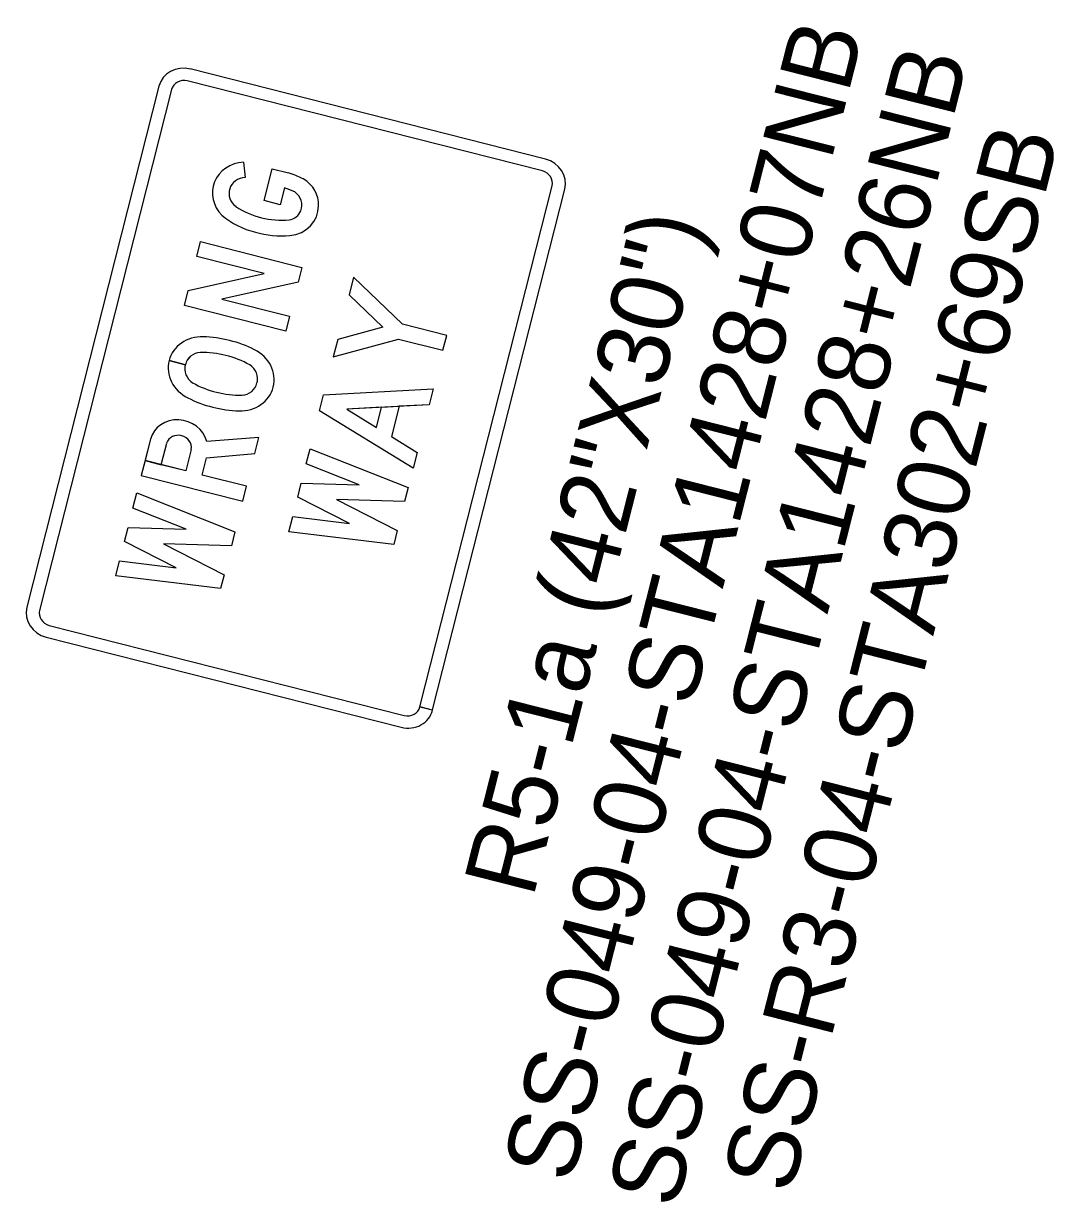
# Model space of a CAD drawing. Extents: x 670257 to 671518, y 737783 to 738188.
# Drawn here: x 670275.413 to 670279.004, y 738123.258 to 738127.359 of the extents above; entities that cross this region are included whole.
import ezdxf

# ---------------------------------------------------------------- set-up
doc = ezdxf.new("R2010")
doc.units = 0
for name, color, linetype in [('GSBWFILL', 7, 'Continuous'), ('GSCOLORFILL', 7, 'Continuous'), ('GSOUTLINE', 7, 'Continuous'), ('R_SIGN_ANNOT', 7, 'Continuous')]:
    doc.layers.add(name, color=color, linetype=linetype)

msp = doc.modelspace()

# ---------------------------------------------------------------- linework, layer by layer
at = {"layer": 'GSBWFILL'}
for p, q in [((670276.1786, 738126.8766), (670276.1849, 738126.8225)), ((670276.1849, 738126.8225), (670276.1849, 738126.8225)), ((670275.9765, 738126.1716), (670275.9196, 738126.186)), ((670275.9196, 738126.186), (670275.9765, 738126.1716)), ((670275.9765, 738126.1716), (670275.9765, 738126.1716))]:
    msp.add_line(p, q, dxfattribs=at)
for points in [[(670276.3216, 738126.7868), (670276.3067, 738126.7282), (670276.2503, 738126.7425), (670276.2784, 738126.8536), (670276.3349, 738126.8393)], [(670275.855, 738125.913), (670275.8361, 738125.8382), (670275.8925, 738125.8239), (670275.9115, 738125.8987)], [(670276.1759, 738125.6967), (670276.189, 738125.7487), (670276.0347, 738125.7878), (670276.05, 738125.8482), (670276.2181, 738125.8634), (670276.2322, 738125.919), (670276.051, 738125.9048)], [(670275.9972, 738125.877), (670275.9782, 738125.8021), (670275.8361, 738125.8382), (670275.8229, 738125.7862), (670276.1759, 738125.6967)]]:
    msp.add_lwpolyline(points, dxfattribs=at)
for points in [[(670276.3259, 738126.2882), (670275.9729, 738126.3777), (670275.9862, 738126.4302), (670276.2511, 738126.4885), (670276.0161, 738126.5481), (670276.0293, 738126.6), (670276.3822, 738126.5105), (670276.3691, 738126.4585), (670276.1028, 738126.4), (670276.339, 738126.3401)], [(670276.4911, 738126.1988), (670276.7183, 738126.2612), (670276.8727, 738126.2221), (670276.8858, 738126.2739), (670276.7315, 738126.313), (670276.5615, 738126.4762), (670276.546, 738126.4152), (670276.6632, 738126.3028), (670276.5066, 738126.2597)], [(670276.7686, 738125.8118), (670276.4436, 738126.0117), (670276.4576, 738126.0668), (670276.8386, 738126.0876), (670276.8247, 738126.0327), (670276.5378, 738126.0171), (670276.6412, 738125.9535), (670276.659, 738126.0237), (670276.72, 738126.027), (670276.6932, 738125.9215), (670276.7825, 738125.8666)], [(670276.5475, 738125.6194), (670276.3674, 738125.7109), (670276.3797, 738125.7596), (670276.5816, 738125.7542), (670276.3969, 738125.8272), (670276.4102, 738125.8796), (670276.7516, 738125.7447), (670276.7393, 738125.6961), (670276.5027, 738125.7025), (670276.7137, 738125.5953), (670276.7014, 738125.5467), (670276.3369, 738125.5908), (670276.3502, 738125.6433)], [(670275.9448, 738125.4654), (670275.7647, 738125.5569), (670275.7771, 738125.6056), (670275.979, 738125.6002), (670275.7942, 738125.6732), (670275.8075, 738125.7257), (670276.149, 738125.5907), (670276.1367, 738125.5421), (670275.9001, 738125.5485), (670276.1111, 738125.4413), (670276.0988, 738125.3927), (670275.7343, 738125.4368), (670275.7476, 738125.4893)]]:
    msp.add_lwpolyline(points, close=True, dxfattribs=at)
for centre, major_axis, start_param, end_param in [((670276.1912, 738126.7651), (-0.1173, 0.0297), 5.047079, 7.269538), ((670276.1896, 738126.7657), (-0.0597, 0.0151), 5.019133, 7.435888), ((670276.2475, 738126.5727), (-0.2958, 0.075), 4.464985, 4.64968), ((670276.3345, 738126.7355), (-0.1022, 0.0259), 3.298379, 4.420063), ((670276.2721, 738126.6219), (-0.1816, 0.0461), 4.467103, 4.672764), ((670276.3219, 738126.7293), (-0.0582, 0.0148), 3.004204, 4.309319), ((670276.3002, 738126.9211), (-0.2585, 0.0656), 1.210526, 1.939684), ((670276.3266, 738126.7261), (-0.1098, 0.0278), 1.917608, 3.396087), ((670276.2784, 738126.8716), (-0.2593, 0.0658), 1.08427, 1.578846), ((670276.3286, 738126.723), (-0.05, 0.0127), 1.967991, 3.075152), ((670276.2971, 738126.8991), (-0.2924, 0.0742), 1.54039, 1.942608), ((670276.0388, 738126.155), (-0.1194, 0.0303), 4.940915, 6.27603), ((670276.0442, 738125.9235), (-0.3622, 0.0919), 4.707364, 4.955713), ((670276.0478, 738125.9226), (-0.3622, 0.0919), 4.469065, 4.717414), ((670276.0358, 738126.1584), (-0.059, 0.015), 5.062003, 6.313732), ((670276.0489, 738125.9612), (-0.2657, 0.0674), 4.688261, 5.016143), ((670276.0617, 738125.9579), (-0.2657, 0.0674), 4.408635, 4.736517), ((670276.1629, 738126.1236), (-0.1194, 0.0303), 3.1486, 4.483863), ((670276.0392, 738126.1566), (-0.1194, 0.0303), 0.007008, 1.34227), ((670276.0349, 738126.1551), (-0.059, 0.015), 6.252339, 7.504367), ((670276.1672, 738126.1251), (-0.059, 0.015), 3.110746, 4.362775), ((670276.1404, 738126.3222), (-0.2657, 0.0674), 1.267042, 1.594924), ((670276.1663, 738126.1217), (-0.059, 0.015), 1.920411, 3.172439), ((670276.1533, 738126.319), (-0.2657, 0.0674), 1.546668, 1.87455), ((670276.1633, 738126.1251), (-0.1194, 0.0303), 1.799323, 3.134585), ((670276.1543, 738126.3575), (-0.3622, 0.0919), 1.327472, 1.575821), ((670276.1579, 738126.3566), (-0.3622, 0.0919), 1.565772, 1.814121), ((670275.9529, 738125.8865), (-0.0983, 0.0249), 3.608399, 6.264838), ((670275.9536, 738125.8852), (-0.043, 0.0109), 3.211299, 6.213479)]:
    msp.add_ellipse(centre, major_axis=major_axis, ratio=0.919391, start_param=start_param, end_param=end_param, dxfattribs=at)
at = {"layer": 'GSCOLORFILL'}
for p, q in [((670277.2291, 738126.8871), (670275.9937, 738127.2005)), ((670275.8846, 738127.1405), (670275.425, 738125.3284)), ((670275.8846, 738127.1405), (670275.425, 738125.3284)), ((670277.2187, 738126.846), (670275.9833, 738127.1593)), ((670275.9287, 738127.1293), (670275.4691, 738125.3172)), ((670276.1786, 738126.8766), (670276.1849, 738126.8225)), ((670276.1849, 738126.8225), (670276.1849, 738126.8225)), ((670276.7929, 738124.982), (670277.2524, 738126.7936)), ((670276.837, 738124.9708), (670277.2965, 738126.7824)), ((670275.9765, 738126.1716), (670275.9196, 738126.186)), ((670275.9196, 738126.186), (670275.9765, 738126.1716)), ((670275.9765, 738126.1716), (670275.9765, 738126.1716)), ((670275.5028, 738125.2649), (670276.7382, 738124.9515)), ((670275.4924, 738125.2237), (670276.7278, 738124.9104)), ((670276.8369, 738124.9703), (670276.7928, 738124.9815)), ((670276.7929, 738124.982), (670276.837, 738124.9708))]:
    msp.add_line(p, q, dxfattribs=at)
for points in [[(670276.3216, 738126.7868), (670276.3067, 738126.7282), (670276.2503, 738126.7425), (670276.2784, 738126.8536), (670276.3349, 738126.8393)], [(670275.855, 738125.913), (670275.8361, 738125.8382), (670275.8925, 738125.8239), (670275.9115, 738125.8987)], [(670276.1759, 738125.6967), (670276.189, 738125.7487), (670276.0347, 738125.7878), (670276.05, 738125.8482), (670276.2181, 738125.8634), (670276.2322, 738125.919), (670276.051, 738125.9048)], [(670275.9972, 738125.877), (670275.9782, 738125.8021), (670275.8361, 738125.8382), (670275.8229, 738125.7862), (670276.1759, 738125.6967)]]:
    msp.add_lwpolyline(points, dxfattribs=at)
for points in [[(670276.3259, 738126.2882), (670275.9729, 738126.3777), (670275.9862, 738126.4302), (670276.2511, 738126.4885), (670276.0161, 738126.5481), (670276.0293, 738126.6), (670276.3822, 738126.5105), (670276.3691, 738126.4585), (670276.1028, 738126.4), (670276.339, 738126.3401)], [(670276.4911, 738126.1988), (670276.7183, 738126.2612), (670276.8727, 738126.2221), (670276.8858, 738126.2739), (670276.7315, 738126.313), (670276.5615, 738126.4762), (670276.546, 738126.4152), (670276.6632, 738126.3028), (670276.5066, 738126.2597)], [(670276.7686, 738125.8118), (670276.4436, 738126.0117), (670276.4576, 738126.0668), (670276.8386, 738126.0876), (670276.8247, 738126.0327), (670276.5378, 738126.0171), (670276.6412, 738125.9535), (670276.659, 738126.0237), (670276.72, 738126.027), (670276.6932, 738125.9215), (670276.7825, 738125.8666)], [(670276.5475, 738125.6194), (670276.3674, 738125.7109), (670276.3797, 738125.7596), (670276.5816, 738125.7542), (670276.3969, 738125.8272), (670276.4102, 738125.8796), (670276.7516, 738125.7447), (670276.7393, 738125.6961), (670276.5027, 738125.7025), (670276.7137, 738125.5953), (670276.7014, 738125.5467), (670276.3369, 738125.5908), (670276.3502, 738125.6433)], [(670275.9448, 738125.4654), (670275.7647, 738125.5569), (670275.7771, 738125.6056), (670275.979, 738125.6002), (670275.7942, 738125.6732), (670275.8075, 738125.7257), (670276.149, 738125.5907), (670276.1367, 738125.5421), (670275.9001, 738125.5485), (670276.1111, 738125.4413), (670276.0988, 738125.3927), (670275.7343, 738125.4368), (670275.7476, 738125.4893)]]:
    msp.add_lwpolyline(points, close=True, dxfattribs=at)
for centre, major_axis, ratio, start_param, end_param in [((670275.9728, 738127.1181), (-0.0882, 0.0224), 0.933392, 4.712389, 6.283185), ((670275.9728, 738127.1181), (-0.0882, 0.0224), 0.933392, 4.712389, 6.283185), ((670275.9728, 738127.1181), (-0.0441, 0.0112), 0.933392, 4.712389, 6.283185), ((670277.2082, 738126.8048), (-0.0882, 0.0224), 0.933392, 3.141593, 4.712389), ((670276.1912, 738126.7651), (-0.1173, 0.0297), 0.919391, 5.047079, 7.269538), ((670277.2082, 738126.8048), (-0.0441, 0.0112), 0.933392, 3.141593, 4.712389), ((670276.1896, 738126.7657), (-0.0597, 0.0151), 0.919391, 5.019133, 7.435888), ((670276.2475, 738126.5727), (-0.2958, 0.075), 0.919391, 4.464985, 4.64968), ((670276.3345, 738126.7355), (-0.1022, 0.0259), 0.919391, 3.298379, 4.420063), ((670276.2721, 738126.6219), (-0.1816, 0.0461), 0.919391, 4.467103, 4.672764), ((670276.3219, 738126.7293), (-0.0582, 0.0148), 0.919391, 3.004204, 4.309319), ((670276.3002, 738126.9211), (-0.2585, 0.0656), 0.919391, 1.210526, 1.939684), ((670276.3266, 738126.7261), (-0.1098, 0.0278), 0.919391, 1.917608, 3.396087), ((670276.2784, 738126.8716), (-0.2593, 0.0658), 0.919391, 1.08427, 1.578846), ((670276.3286, 738126.723), (-0.05, 0.0127), 0.919391, 1.967991, 3.075152), ((670276.2971, 738126.8991), (-0.2924, 0.0742), 0.919391, 1.54039, 1.942608), ((670276.0388, 738126.155), (-0.1194, 0.0303), 0.919391, 4.940915, 6.27603), ((670276.0442, 738125.9235), (-0.3622, 0.0919), 0.919391, 4.707364, 4.955713), ((670276.0478, 738125.9226), (-0.3622, 0.0919), 0.919391, 4.469065, 4.717414), ((670276.0358, 738126.1584), (-0.059, 0.015), 0.919391, 5.062003, 6.313732), ((670276.0489, 738125.9612), (-0.2657, 0.0674), 0.919391, 4.688261, 5.016143), ((670276.0617, 738125.9579), (-0.2657, 0.0674), 0.919391, 4.408635, 4.736517), ((670276.1629, 738126.1236), (-0.1194, 0.0303), 0.919391, 3.1486, 4.483863), ((670276.0392, 738126.1566), (-0.1194, 0.0303), 0.919391, 0.007008, 1.34227), ((670276.0349, 738126.1551), (-0.059, 0.015), 0.919391, 6.252339, 7.504367), ((670276.1672, 738126.1251), (-0.059, 0.015), 0.919391, 3.110746, 4.362775), ((670276.1404, 738126.3222), (-0.2657, 0.0674), 0.919391, 1.267042, 1.594924), ((670276.1663, 738126.1217), (-0.059, 0.015), 0.919391, 1.920411, 3.172439), ((670276.1533, 738126.319), (-0.2657, 0.0674), 0.919391, 1.546668, 1.87455), ((670276.1633, 738126.1251), (-0.1194, 0.0303), 0.919391, 1.799323, 3.134585), ((670276.1543, 738126.3575), (-0.3622, 0.0919), 0.919391, 1.327472, 1.575821), ((670276.1579, 738126.3566), (-0.3622, 0.0919), 0.919391, 1.565772, 1.814121), ((670275.9529, 738125.8865), (-0.0983, 0.0249), 0.919391, 3.608399, 6.264838), ((670275.9536, 738125.8852), (-0.043, 0.0109), 0.919391, 3.211299, 6.213479), ((670275.5133, 738125.3061), (-0.0882, 0.0224), 0.933392, 0, 1.570796), ((670275.5133, 738125.3061), (-0.0441, 0.0112), 0.933392, 0, 1.570796), ((670276.7487, 738124.9927), (-0.0882, 0.0224), 0.933392, 1.570796, 3.141593), ((670276.7487, 738124.9927), (-0.0441, 0.0112), 0.933392, 1.570796, 3.141593)]:
    msp.add_ellipse(centre, major_axis=major_axis, ratio=ratio, start_param=start_param, end_param=end_param, dxfattribs=at)
at = {"layer": 'GSOUTLINE'}
for p, q in [((670276.1786, 738126.8766), (670276.1849, 738126.8225)), ((670276.1849, 738126.8225), (670276.1849, 738126.8225)), ((670275.9972, 738125.877), (670275.9782, 738125.8021))]:
    msp.add_line(p, q, dxfattribs=at)
for points in [[(670276.3216, 738126.7868), (670276.3067, 738126.7282), (670276.2503, 738126.7425), (670276.2784, 738126.8536), (670276.3349, 738126.8393)], [(670275.855, 738125.913), (670275.8229, 738125.7862), (670276.1759, 738125.6967), (670276.189, 738125.7487), (670276.0347, 738125.7878), (670276.05, 738125.8482)], [(670276.05, 738125.8482), (670276.2181, 738125.8634), (670276.2322, 738125.919), (670276.051, 738125.9048)], [(670275.9782, 738125.8021), (670275.8925, 738125.8239), (670275.9115, 738125.8987)]]:
    msp.add_lwpolyline(points, dxfattribs=at)
for points in [[(670276.3259, 738126.2882), (670275.9729, 738126.3777), (670275.9862, 738126.4302), (670276.2511, 738126.4885), (670276.0161, 738126.5481), (670276.0293, 738126.6), (670276.3822, 738126.5105), (670276.3691, 738126.4585), (670276.1028, 738126.4), (670276.339, 738126.3401)], [(670276.4911, 738126.1988), (670276.7183, 738126.2612), (670276.8727, 738126.2221), (670276.8858, 738126.2739), (670276.7315, 738126.313), (670276.5615, 738126.4762), (670276.546, 738126.4152), (670276.6632, 738126.3028), (670276.5066, 738126.2597)], [(670276.6932, 738125.9215), (670276.7825, 738125.8666), (670276.7686, 738125.8118), (670276.4436, 738126.0117), (670276.4576, 738126.0668), (670276.8386, 738126.0876), (670276.8247, 738126.0327), (670276.72, 738126.027)], [(670276.6412, 738125.9535), (670276.659, 738126.0237), (670276.5378, 738126.0171)], [(670276.5475, 738125.6194), (670276.3674, 738125.7109), (670276.3797, 738125.7596), (670276.5816, 738125.7542), (670276.3969, 738125.8272), (670276.4102, 738125.8796), (670276.7516, 738125.7447), (670276.7393, 738125.6961), (670276.5027, 738125.7025), (670276.7137, 738125.5953), (670276.7014, 738125.5467), (670276.3369, 738125.5908), (670276.3502, 738125.6433)], [(670275.9448, 738125.4654), (670275.7647, 738125.5569), (670275.7771, 738125.6056), (670275.979, 738125.6002), (670275.7942, 738125.6732), (670275.8075, 738125.7257), (670276.149, 738125.5907), (670276.1367, 738125.5421), (670275.9001, 738125.5485), (670276.1111, 738125.4413), (670276.0988, 738125.3927), (670275.7343, 738125.4368), (670275.7476, 738125.4893)]]:
    msp.add_lwpolyline(points, close=True, dxfattribs=at)
for centre, major_axis, start_param, end_param in [((670276.1912, 738126.7651), (-0.1173, 0.0297), 5.047079, 7.269538), ((670276.1896, 738126.7657), (-0.0597, 0.0151), 5.019133, 7.435888), ((670276.2475, 738126.5727), (-0.2958, 0.075), 4.464985, 4.64968), ((670276.3345, 738126.7355), (-0.1022, 0.0259), 3.298379, 4.420063), ((670276.2721, 738126.6219), (-0.1816, 0.0461), 4.467103, 4.672764), ((670276.3219, 738126.7293), (-0.0582, 0.0148), 3.004204, 4.309319), ((670276.3002, 738126.9211), (-0.2585, 0.0656), 1.210526, 1.939684), ((670276.3266, 738126.7261), (-0.1098, 0.0278), 1.917608, 3.396087), ((670276.2784, 738126.8716), (-0.2593, 0.0658), 1.08427, 1.578846), ((670276.3286, 738126.723), (-0.05, 0.0127), 1.967991, 3.075152), ((670276.2971, 738126.8991), (-0.2924, 0.0742), 1.54039, 1.942608), ((670276.0388, 738126.155), (-0.1194, 0.0303), 4.940915, 6.276178), ((670276.0442, 738125.9235), (-0.3622, 0.0919), 4.707364, 4.955713), ((670276.0478, 738125.9226), (-0.3622, 0.0919), 4.469065, 4.717414), ((670276.0358, 738126.1584), (-0.059, 0.015), 5.062003, 6.314032), ((670276.0489, 738125.9612), (-0.2657, 0.0674), 4.688261, 5.016143), ((670276.0617, 738125.9579), (-0.2657, 0.0674), 4.408635, 4.736517), ((670276.1629, 738126.1236), (-0.1194, 0.0303), 3.1486, 4.483863), ((670276.0392, 738126.1566), (-0.1194, 0.0303), 0.007008, 1.34227), ((670276.0349, 738126.1551), (-0.059, 0.015), 6.252339, 7.504367), ((670276.1672, 738126.1251), (-0.059, 0.015), 3.110746, 4.362774), ((670276.1404, 738126.3222), (-0.2657, 0.0674), 1.267043, 1.594924), ((670276.1663, 738126.1217), (-0.059, 0.015), 1.920411, 3.172439), ((670276.1533, 738126.319), (-0.2657, 0.0674), 1.546668, 1.87455), ((670276.1633, 738126.1251), (-0.1194, 0.0303), 1.799323, 3.134585), ((670276.1543, 738126.3575), (-0.3622, 0.0919), 1.327472, 1.575821), ((670276.1579, 738126.3566), (-0.3622, 0.0919), 1.565772, 1.814121), ((670275.9529, 738125.8865), (-0.0983, 0.0249), 3.608399, 6.264838), ((670275.9536, 738125.8852), (-0.043, 0.0109), 3.211299, 6.213479)]:
    msp.add_ellipse(centre, major_axis=major_axis, ratio=0.919391, start_param=start_param, end_param=end_param, dxfattribs=at)

# ---------------------------------------------------------------- texts
at = {"layer": 'R_SIGN_ANNOT'}
for s, p in [('SS-049-04-STA1428+07NB', (670277.3209, 738123.3191)), ('SS-049-04-STA1428+26NB', (670277.6853, 738123.2307)), ('SS-R3-04-STA302+69SB', (670278.0851, 738123.2816)), ('R5-1a (42"X30")', (670277.186, 738124.3128))]:
    msp.add_text(s, height=0.25, rotation=75.7686, dxfattribs=at).set_placement(p)

doc.saveas('drawing.dxf')
